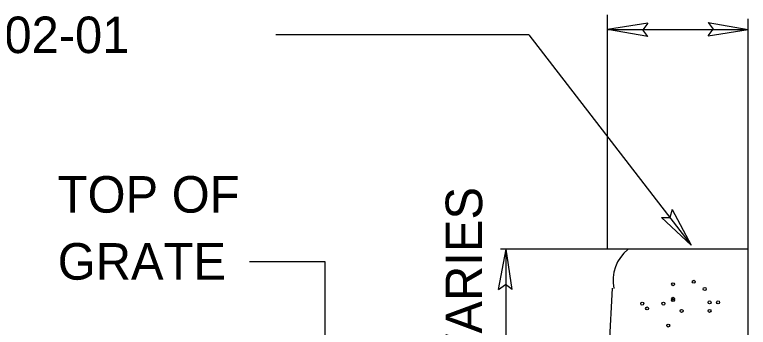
# Model space of a CAD drawing. Extents: x 9.6 to 16.8, y 2.2 to 12.2.
# Drawn here: x 15.034 to 16.239, y 8.912 to 9.425 of the extents above; entities that cross this region are included whole.
import ezdxf

# ---------------------------------------------------------------- set-up
doc = ezdxf.new("R2010")
doc.units = 0
for name, color, linetype in [('DETL-DIMS', 7, 'Continuous'), ('DETL-LINE', 7, 'Continuous'), ('DETL-NOTE', 7, 'Continuous'), ('DETL-PATT', 7, 'Continuous')]:
    doc.layers.add(name, color=color, linetype=linetype)

msp = doc.modelspace()

# ---------------------------------------------------------------- linework, layer by layer
at = {"layer": 'DETL-DIMS'}
for p, q in [((16.0076, 9.04), (16.0076, 9.4252)), ((16.173, 9.4123), (16.2388, 9.4008)), ((16.173, 9.4123), (16.1812, 9.4013)), ((16.2388, 9.04), (16.2388, 9.4183)), ((16.0736, 9.4112), (16.0076, 9.4008)), ((16.0735, 9.3893), (16.0076, 9.4008)), ((16.0076, 9.4008), (16.2388, 9.4008)), ((16.0736, 9.4112), (16.0653, 9.4003)), ((16.0735, 9.3893), (16.0653, 9.4003)), ((16.1729, 9.3904), (16.1812, 9.4013)), ((16.1729, 9.3904), (16.2388, 9.4008)), ((15.8785, 9.3921), (15.4629, 9.3921)), ((15.8785, 9.3921), (16.1451, 9.0467)), ((16.1136, 9.1056), (16.1099, 9.0924)), ((16.1136, 9.1056), (16.1451, 9.0467)), ((16.0962, 9.0922), (16.1099, 9.0924)), ((16.0962, 9.0922), (16.1451, 9.0467)), ((15.8287, 8.9743), (15.8408, 9.04)), ((16.0409, 9.04), (15.8319, 9.04)), ((15.8507, 8.974), (15.8408, 9.04)), ((15.8408, 8.8211), (15.8408, 9.04)), ((15.4196, 9.0202), (15.5431, 9.0202)), ((15.5431, 9.0202), (15.5431, 8.8409)), ((15.8287, 8.9743), (15.8398, 8.9824)), ((15.8507, 8.974), (15.8398, 8.9824))]:
    msp.add_line(p, q, dxfattribs=at)
at = {"layer": 'DETL-LINE'}
for p, q in [((16.2388, 9.04), (16.0409, 9.04)), ((16.2382, 8.6921), (16.2388, 9.04)), ((16.0076, 8.8136), (16.0155, 8.9764))]:
    msp.add_line(p, q, dxfattribs=at)
msp.add_arc((16.0818, 8.9891), 0.0652, 128.7955, 191.6614, dxfattribs=at)
at = {"layer": 'DETL-PATT'}
for centre in [(16.1153, 8.9828), (16.1493, 8.9868), (16.1672, 8.9748), (16.1153, 8.9588), (16.1153, 8.9568), (16.1752, 8.9529), (16.1892, 8.9529), (16.0645, 8.9509), (16.0725, 8.9429), (16.0994, 8.9509), (16.1293, 8.9389), (16.1752, 8.9389), (16.1073, 8.9149)]:
    msp.add_circle(centre, 0.00247, dxfattribs=at)

# ---------------------------------------------------------------- texts
at = {"layer": 'DETL-NOTE'}
for s, p in [('MD 620.02-01', (14.7136, 9.3621)), ('TOP OF', (15.1044, 9.1002)), ('GRATE', (15.1044, 8.9902))]:
    msp.add_text(s, height=0.06, dxfattribs=at).set_placement(p)
msp.add_text('VARIES', height=0.06, rotation=90, dxfattribs=at).set_placement((15.8016, 8.8481))

doc.saveas('drawing.dxf')
